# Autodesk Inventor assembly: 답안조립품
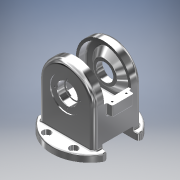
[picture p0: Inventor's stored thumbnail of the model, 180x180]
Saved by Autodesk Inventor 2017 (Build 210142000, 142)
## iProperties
Part Number: 답안조립품
Material: 일반
Document SubType Name: Assembly
Designer: MRC
Author: MRC
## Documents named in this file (2)
- C:\Users\MRC\Desktop\740804V1010\답안조립품.iam
- C:\Users\MRC\Desktop\740804V1010\본체.ipt
